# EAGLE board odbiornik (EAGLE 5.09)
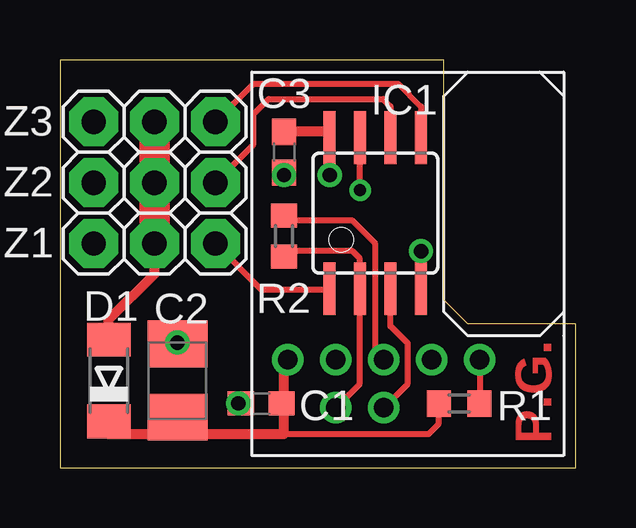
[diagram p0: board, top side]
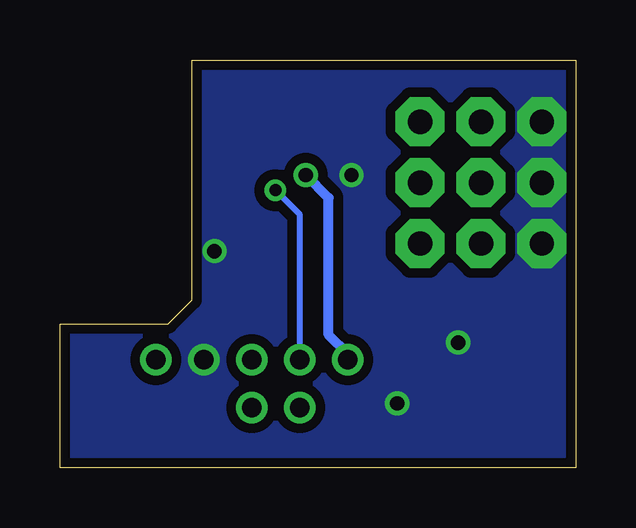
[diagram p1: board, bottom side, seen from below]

Size 21.5 x 17 mm. Coordinates in mm from the lower left corner, seen from the top.
Outline: 0,0 21.5,0 21.5,6 17,6 16,7 16,17 0,17 0,0
Copper layers (1*16): Top 0.035mm / dielectric 1.5mm / Bottom 0.035mm
Design rules "default *": minimum track width 10mil, minimum drill 24mil, track to track 8mil, track to pad 8mil, pad to pad 8mil, via to via 8mil, smd to smd 8mil, copper to edge 1mil, drill to drill 8mil, minimum pad ring 10mil, minimum via ring 8mil, stop-mask expansion 4mil, vias tented up to drill 0mil, thermal gap 10mil

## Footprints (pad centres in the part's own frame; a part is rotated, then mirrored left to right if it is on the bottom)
C0603 = smd 1.1 x 1: 1 -0.85,0; 2 0.85,0
B/3528-21R = smd 1.95 x 2.5: + 1.525,0; - -1.525,0
MINIMELF = smd 1.4 x 1.8: A 1.7,0; C -1.7,0
SOIC8 = smd 0.5 x 2.2: 1 -1.905,-3.154; 2 -0.645,-3.154; 3 0.625,-3.154; 4 1.895,-3.154; 5 1.905,3.154; 6 0.635,3.154; 7 -0.635,3.154; 8 -1.905,3.154
R0603 = smd 1 x 1.1: 1 -0.85,0; 2 0.85,0
RFM01M3 = drill 0.8 round: 2 8,2; 3 6,2; 8 2,0; 9 4,0; 10 6,0; 11 8,0; 12 10,0
PINHEAD-1X3B = drill 1.016 pad 2.032 octagon: 1 -2.54,0; 2 0,0; 3 2.54,0

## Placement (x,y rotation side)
C1  100nF  [C0603]  8.39,2.67 180 top
C2  47uF/10V  [B/3528-21R]  4.9,3.63 270 top
C3  100nF  [C0603]  9.34,13.15 270 top
D1  BAS85  [MINIMELF]  2.04,3.63 90 top
IC1  ATTINY13  [SOIC8]  13.15,10.61 0 top
R1  10k  [R0603]  16.64,2.67 180 top
R2  4k7  [R0603]  9.34,9.66 90 top
RFM01  [RFM01M3]  19.5,4.5 180 top
Z1  [PINHEAD-1X3B]  3.95,9.34 0 top
Z2  [PINHEAD-1X3B]  3.95,11.88 0 top
Z3  [PINHEAD-1X3B]  3.95,14.42 0 top

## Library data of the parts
C1-C3 R1 R2 = rcl
D1 = diode
IC1 = avr
RFM01 Z1-Z3 = gogo

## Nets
GND: C1.2 C2.- C3.2 IC1.4 RFM01.9 Z1.1 Z2.1 Z3.1
N$1: IC1.1 Z1.3
N$2: R2.2 RFM01.10
N$3: IC1.7 RFM01.11
N$4: IC1.5 Z3.3
N$5: IC1.2 R2.1 RFM01.2
N$6: R1.1 RFM01.8
N$7: IC1.3 RFM01.3
N$8: IC1.6 Z2.3
N$9: D1.A Z1.2 Z2.2 Z3.2
VCC: C1.1 C2.+ C3.1 D1.C IC1.8 R1.2 RFM01.12

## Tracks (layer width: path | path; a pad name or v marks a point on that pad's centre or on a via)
GND  (via drill 0.6)
  Top 0.406: C1.2 v7.44,2.67 | C2.- v4.9,5.21 | C3.2 v9.34,12.2 | IC1.4 v15.06,9.03
  pour Bottom (isolate 0.406, no thermals): 0.5,16.5 21,16.5 21,0.5 0.5,0.5
N$1
  Top 0.254: IC1.1 11.25,7.44 8.39,7.44 Z1.3
N$2
  Top 0.254: RFM01.10 13.15,4.85 13.15,9.34 12.2,10.29 9.34,10.29 R2.2
N$3  (via drill 0.5)
  Top 0.254: v12.52,11.56 IC1.7
  Bottom 0.254: RFM01.11 11.5,10.55 v12.52,11.56
N$4
  Top 0.254: IC1.5 15.06,15.06 14.11,16.01 8.07,16.01 Z3.3
N$5
  Top 0.254: R2.1 9.34,9.03 12.2,9.03 12.51,8.72 IC1.2 12.51,5.22 12.5,5.22 12.5,3.5 RFM01.2
N$6
  Top 0.254: R1.1 RFM01.8
N$7
  Top 0.254: RFM01.3 14.5,3.5 14.5,5.18 13.78,5.91 IC1.3
N$8
  Top 0.254: IC1.6 13.79,15.06 13.47,15.38 8.71,15.38 8.07,14.74 8.07,13.47 Z2.3
N$9
  Top 0.406: D1.A 2.04,6.17 3.95,8.07 Z1.2
  Top 1.27: Z3.2 Z2.2 Z1.2
VCC  (via drill 0.6)
  Top 0.254: R1.2 15.8,1.83 15.38,1.41 9.34,1.41
  Top 0.406: D1.C 2.04,1.41 4.9,1.41 | 4.9,1.41 C2.+ | 4.9,1.41 9.34,1.41 9.34,2.67 | 9.34,2.67 C1.1 | 9.34,2.67 9.34,4.5 RFM01.12 | v11.25,12.2 IC1.8 11.25,14 C3.1
  Bottom 0.406: RFM01.12 9.5,4.74 10.29,5.53 10.29,11.25 v11.25,12.2

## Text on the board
Top: P.G.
